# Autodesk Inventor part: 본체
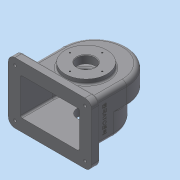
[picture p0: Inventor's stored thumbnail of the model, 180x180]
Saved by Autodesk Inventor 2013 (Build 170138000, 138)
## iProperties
Created: 2017-11
Part Number: 본체
Material: 일반
Document SubType Name: Modeling
Designer: dgall
Density: 1 g/cm^3
Author: dgall
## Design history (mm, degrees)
sketch "스케치3"
  geometry: L1 (-58, 0)-(-58, -80); L2 (-58, -80)-(58, -80); L3 (58, -80)-(58, 0); A1 r 58 centre (0, 0) between (58, 0) and (-58, 0); 1 further point
  constraints: 6 end point, 2 point on circle, 2 tangent, 1 centre point, 1 coincident, 1 horizontal alignment, 1 perpendicular, 1 vertical
  dimensions: "d8" = 58 radius of A1; "d9" = 80 distance of L1.start L1.end
extrude "돌출2" new body sketch "스케치3" stored distance "d10" = 38; taper "d11" = 0 deg
sketch "스케치4"
  geometry: L1 (-58, 0)-(-58, -80) reference; L2 (-58, -80)-(58, -80) reference; L3 (58, -80)-(58, 0) reference; L4 (-58, -23)-(-58, -80); L5 (58, -80)-(-58, -80); L6 (58, -80)-(58, -23); A1 r 58 centre (0, 0) between (58, 0) and (-58, 0) reference; A2 r 58 centre (0, -23) between (58, -23) and (-58, -23)
  constraints: 6 end point, 2 collinear, 2 point on circle, 2 point on line, 1 centre point, 1 vertical alignment
  dimensions: "d12" = 58 radius of A2; "d13" = 57 distance from line of A2.centre L2
extrude "돌출3" join sketch "스케치4" distance "d14" = 38; taper "d15" = 0 deg
feature "쉘1" dims "d16" = 5
sketch "스케치5"
  geometry: L1 (5, -71)-(5, -5) reference; L2 (116, 0)-(116, -76) reference; L3 (0, 0)-(116, 0) reference; L4 (0, 0)-(0, -76) reference; L5 (116, -76)-(0, -76) reference; L6 (-17, 17)-(133, 17); L7 (133, 17)-(133, -93); L8 (133, -93)-(-17, -93); L9 (-17, -93)-(-17, 17); 4 further points
  constraints: 8 end point, 3 midpoint, 2 parallel, 1 horizontal, 1 horizontal alignment, 1 perpendicular, 1 vertical alignment
  dimensions: "d17" = 110 distance of L8.end L6.start; "d19" = 150 distance of L7.end L8.end
extrude "돌출4" join sketch "스케치5" distance "d20" = 15; taper "d21" = 0 deg
node "작업 평면3"
sketch "스케치6"
  geometry: C1 r 6 at (-75, -36); 1 further point
  constraints: 1 centre point, 1 coincident
  dimensions: "d24" = 12 diameter of C1
extrude "돌출5" join sketch "스케치6" stored distance "d25" = 15; taper "d26" = 0 deg
sketch "스케치7"
  geometry: C1 r 6 at (0, 0) reference; 1 further point
  constraints: 1 coincident
hole "구멍1" sketch "스케치7" at (0, 0) diameter "d27" = 4.459; stored, may be unused: countersink angle "d31" = 90 deg, drill point angle "d33" = 118 deg; dims "d28" = 6, "d29" = 4, "d30" = 2, "d32" = 8
sketch "스케치8"
  geometry: L1 (-75, -80)-(75, -80) reference; C1 r 37.5 at (0, -15); A1 r 58 centre (0, 0) between (58, 0) and (-58, 0) reference
  constraints: 1 centre point, 1 vertical alignment
  dimensions: "d34" = 75 diameter of C1; "d35" = 65 distance from line of C1.centre L1
extrude "돌출6" join sketch "스케치8" distance "d36" = 9; taper "d37" = 0 deg
sketch "스케치9"
  geometry: L1 (-75, -80)-(75, -80) reference; C1 r 31 at (0, -15); 1 further point
  constraints: 1 centre point, 1 vertical alignment
  dimensions: "d41" = 62 diameter of C1; "d42" = 65 distance from line of L1 C1.centre
extrude "돌출7" join sketch "스케치9" distance "d43" = 10; taper "d44" = 0 deg
sketch "스케치10"
  geometry: C1 r 31 at (0, 0) reference; 2 further points
  constraints: 1 coincident
hole "구멍2" sketch "스케치10" at (0, 0) diameter "d45" = 32; stored, may be unused: countersink angle "d49" = 90 deg, drill point angle "d51" = 118 deg; dims "d46" = 6, "d47" = 4, "d48" = 2, "d50" = 8
sketch "스케치11" dims "d52" = 52
  geometry: C1 r 31 at (0, 0) reference; 3 further points
  constraints: 2 vertical alignment, 1 coincident, 2 other
hole "구멍3" sketch "스케치11" at (0, 26) diameter "d53" = 2.459; stored, may be unused: countersink angle "d57" = 90 deg, drill point angle "d59" = 118 deg; dims "d54" = 6, "d55" = 4, "d56" = 2, "d58" = 8
sketch "스케치12" dims "d63" = 58
  geometry: C1 r 37.5 at (0, 0) reference; 3 further points
  constraints: 2 vertical alignment, 1 coincident, 2 other
hole "구멍4" sketch "스케치12" at (0, 29) diameter "d64" = 2.459; stored, may be unused: countersink angle "d68" = 90 deg, drill point angle "d70" = 118 deg; dims "d65" = 6, "d66" = 4, "d67" = 2, "d69" = 8
fillet "모깎기1" dims "d74" = 12
sketch "스케치13"
  geometry: A1 r 12 centre (-5, 81) between (-5, 93) and (-17, 81) reference; A2 r 12 centre (-5, -5) between (-17, -5) and (-5, -17) reference; A3 r 12 centre (121, -5) between (121, -17) and (133, -5) reference; A4 r 12 centre (121, 81) between (133, 81) and (121, 93) reference; 5 further points
  constraints: 4 coincident
hole "구멍5" sketch "스케치13" at (-5, -5), (-5, 81), (121, 81), (121, -5) diameter "d75" = 5; stored, may be unused: countersink angle "d79" = 90 deg, drill point angle "d81" = 118 deg; dims "d76" = 6, "d77" = 12, "d78" = 5, "d80" = 8
chamfer "모따기1" distance "d82" = 1; stored, may be unused: second distance "d83" = 2, angle "d84" = 45 deg
chamfer "모따기2" distance "d85" = 1; stored, may be unused: second distance "d86" = 2, angle "d87" = 45 deg
fillet "모깎기2" dims "d88" = 8
fillet "모깎기3" dims "d89" = 3
fillet "모깎기4" dims "d90" = 3
fillet "모깎기5" dims "d91" = 8
fillet "모깎기7" dims "d93" = 3
fillet "모깎기8" dims "d94" = 3
sketch "스케치14"
  geometry: L1 (-8, 65)-(-8, 0) reference; L2 (-25, -3)-(-25, -15) reference; L3 (-13, -15)-(-25, -15) reference; 2 further points
  constraints: 1 other
  dimensions: "d95" = 40 distance from line of L3 point (30, 25); "d96" = 38 distance from line of point (30, 25) L1
feature "엠보싱1" sketch "스케치14" dims "d8" = 58, "d9" = 80, "d97" = 0.5, "d98" = 0
fillet "모깎기9" dims "d99" = 3
node "솔리드2"
pattern_circular "원형 패턴1" dims angle "d61" = 360 deg
pattern_circular "원형 패턴2" dims angle "d72" = 360 deg
other parameters: "d22" = -144
